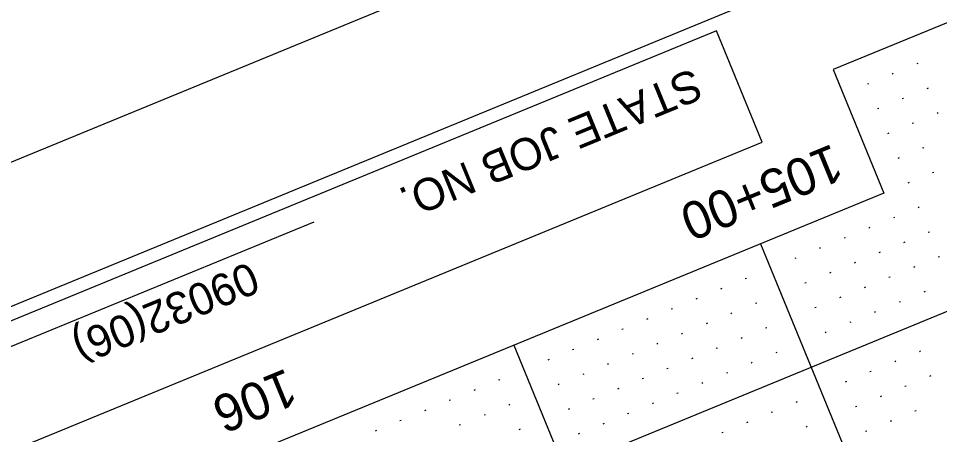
# Model space of a CAD drawing. Extents: x 2148770 to 2150891, y 142633 to 144465.
# Drawn here: x 2148940.4 to 2149113.1, y 143698.4 to 143776.3 of the extents above; entities that cross this region are included whole.
import ezdxf

# ---------------------------------------------------------------- set-up
doc = ezdxf.new("R2010")
doc.units = 0
for name, color, linetype in [('SHT_Plan_Profile_Sheet_Sta_Txt', 7, 'Continuous'), ('SHT_Plan_Profile_Sheet_Txt', 7, 'Continuous'), ('SHT_Plot_Shape_Half', 7, 'Continuous'), ('SHT_Profile_Grid_Major', 7, 'Continuous'), ('SHT_Profile_Grid_Minor', 7, 'Continuous'), ('SHT_Sheet_Border', 7, 'Continuous'), ('SHT_Standard_Sheet_Lines', 7, 'Continuous')]:
    doc.layers.add(name, color=color, linetype=linetype)

msp = doc.modelspace()

# ---------------------------------------------------------------- linework, layer by layer
at = {"layer": 'SHT_Plot_Shape_Half'}
msp.add_lwpolyline([(2150799.14, 143324.02), (2149226.52, 142678.36), (2148808.74, 143695.93), (2150381.36, 144341.59)], close=True, dxfattribs=at)
at = {"layer": 'SHT_Profile_Grid_Major'}
for p, q in [((2150326.3, 144218.99), (2148869.31, 143620.81)), ((2149079.52, 143734.14), (2149259.93, 143294.73)), ((2149033.27, 143715.15), (2149213.67, 143275.74))]:
    msp.add_line(p, q, dxfattribs=at)
at = {"layer": 'SHT_Profile_Grid_Minor'}
for p, q in [((2149109.04, 143767.88), (2149108.81, 143767.78)), ((2149104.42, 143765.98), (2149104.19, 143765.88)), ((2149099.79, 143764.08), (2149099.56, 143763.98)), ((2149110.94, 143763.25), (2149110.71, 143763.16)), ((2149106.32, 143761.35), (2149106.09, 143761.26)), ((2149101.69, 143759.45), (2149101.46, 143759.36)), ((2149112.84, 143758.63), (2149112.61, 143758.53)), ((2149108.22, 143756.73), (2149107.98, 143756.63)), ((2149103.59, 143754.83), (2149103.36, 143754.73)), ((2149110.12, 143752.1), (2149109.88, 143752.01)), ((2149105.49, 143750.2), (2149105.26, 143750.11)), ((2149112.01, 143747.48), (2149111.78, 143747.38)), ((2149107.39, 143745.58), (2149107.16, 143745.48)), ((2149109.29, 143740.95), (2149109.06, 143740.86)), ((2149104.66, 143739.05), (2149104.43, 143738.96)), ((2149100.04, 143737.15), (2149099.81, 143737.06)), ((2149111.19, 143736.33), (2149110.96, 143736.23)), ((2149095.41, 143735.25), (2149095.18, 143735.16)), ((2149106.56, 143734.43), (2149106.33, 143734.33)), ((2149090.79, 143733.36), (2149090.56, 143733.26)), ((2149101.94, 143732.53), (2149101.7, 143732.43)), ((2149086.16, 143731.46), (2149085.93, 143731.36)), ((2149097.31, 143730.63), (2149097.08, 143730.53)), ((2149113.09, 143731.7), (2149112.85, 143731.61)), ((2149092.69, 143728.73), (2149092.45, 143728.64)), ((2149108.46, 143729.8), (2149108.23, 143729.71)), ((2149076.91, 143727.66), (2149076.68, 143727.56)), ((2149103.84, 143727.9), (2149103.6, 143727.81)), ((2149072.29, 143725.76), (2149072.05, 143725.66)), ((2149088.06, 143726.83), (2149087.83, 143726.74)), ((2149099.21, 143726), (2149098.98, 143725.91)), ((2149067.66, 143723.86), (2149067.43, 143723.77)), ((2149094.58, 143724.11), (2149094.35, 143724.01)), ((2149110.36, 143725.18), (2149110.13, 143725.08)), ((2149063.03, 143721.96), (2149062.8, 143721.87)), ((2149078.81, 143723.03), (2149078.58, 143722.94)), ((2149089.96, 143722.21), (2149089.73, 143722.11)), ((2149105.73, 143723.28), (2149105.5, 143723.18)), ((2149058.41, 143720.06), (2149058.18, 143719.97)), ((2149074.18, 143721.13), (2149073.95, 143721.04)), ((2149101.11, 143721.38), (2149100.88, 143721.28)), ((2149069.56, 143719.24), (2149069.33, 143719.14)), ((2149080.71, 143718.41), (2149080.48, 143718.31)), ((2149096.48, 143719.48), (2149096.25, 143719.38)), ((2149053.78, 143718.16), (2149053.55, 143718.07)), ((2149064.93, 143717.34), (2149064.7, 143717.24)), ((2149091.86, 143717.58), (2149091.63, 143717.49)), ((2149049.16, 143716.26), (2149048.93, 143716.17)), ((2149060.31, 143715.44), (2149060.08, 143715.34)), ((2149076.08, 143716.51), (2149075.85, 143716.41)), ((2149044.53, 143714.37), (2149044.3, 143714.27)), ((2149055.68, 143713.54), (2149055.45, 143713.44)), ((2149071.46, 143714.61), (2149071.23, 143714.52)), ((2149082.61, 143713.78), (2149082.38, 143713.69)), ((2149109.53, 143714.03), (2149109.3, 143713.93)), ((2149039.91, 143712.47), (2149039.68, 143712.37)), ((2149051.06, 143711.64), (2149050.83, 143711.54)), ((2149066.83, 143712.71), (2149066.6, 143712.62)), ((2149077.98, 143711.88), (2149077.75, 143711.79)), ((2149104.91, 143712.13), (2149104.68, 143712.03)), ((2149046.43, 143709.74), (2149046.2, 143709.65)), ((2149062.21, 143710.81), (2149061.98, 143710.72)), ((2149073.36, 143709.98), (2149073.13, 143709.89)), ((2149100.28, 143710.23), (2149100.05, 143710.13)), ((2149030.66, 143708.67), (2149030.43, 143708.57)), ((2149057.58, 143708.91), (2149057.35, 143708.82)), ((2149068.73, 143708.09), (2149068.5, 143707.99)), ((2149095.66, 143708.33), (2149095.42, 143708.23)), ((2149111.43, 143709.4), (2149111.2, 143709.31)), ((2149026.03, 143706.77), (2149025.8, 143706.67)), ((2149041.81, 143707.84), (2149041.58, 143707.75)), ((2149052.96, 143707.01), (2149052.73, 143706.92)), ((2149106.81, 143707.5), (2149106.57, 143707.41)), ((2149021.41, 143704.87), (2149021.18, 143704.78)), ((2149048.33, 143705.11), (2149048.1, 143705.02)), ((2149064.11, 143706.19), (2149063.87, 143706.09)), ((2149086.41, 143704.53), (2149086.17, 143704.44)), ((2149102.18, 143705.6), (2149101.95, 143705.51)), ((2149016.78, 143702.97), (2149016.55, 143702.88)), ((2149032.56, 143704.04), (2149032.32, 143703.95)), ((2149043.71, 143703.22), (2149043.47, 143703.12)), ((2149059.48, 143704.29), (2149059.25, 143704.19)), ((2149097.56, 143703.7), (2149097.32, 143703.61)), ((2149108.7, 143702.88), (2149108.47, 143702.78)), ((2149012.16, 143701.07), (2149011.92, 143700.98)), ((2149027.93, 143702.14), (2149027.7, 143702.05)), ((2149054.86, 143702.39), (2149054.62, 143702.29)), ((2149081.78, 143702.63), (2149081.55, 143702.54)), ((2149023.31, 143700.25), (2149023.07, 143700.15)), ((2149034.46, 143699.42), (2149034.22, 143699.32)), ((2149050.23, 143700.49), (2149050, 143700.39)), ((2149077.15, 143700.73), (2149076.92, 143700.64)), ((2149088.3, 143699.91), (2149088.07, 143699.81)), ((2149104.08, 143700.98), (2149103.85, 143700.88)), ((2149007.53, 143699.17), (2149007.3, 143699.08)), ((2149045.6, 143698.59), (2149045.37, 143698.5)), ((2149072.53, 143698.83), (2149072.3, 143698.74)), ((2149099.45, 143699.08), (2149099.22, 143698.98))]:
    msp.add_line(p, q, dxfattribs=at)
at = {"layer": 'SHT_Sheet_Border'}
msp.add_line((2150307.31, 144265.25), (2149093.15, 143766.76), dxfattribs=at)
for points in [[(2150699.45, 143310.11), (2149242.47, 142711.93), (2148843.68, 143683.25), (2150300.66, 144281.43)], [(2149079.81, 143753.17), (2149071.27, 143773.99), (2148846.94, 143681.89), (2148855.48, 143661.07)]]:
    msp.add_lwpolyline(points, close=True, dxfattribs=at)
msp.add_lwpolyline([(2149093.15, 143766.76), (2149102.65, 143743.63), (2148894.51, 143658.18)], dxfattribs=at)
at = {"layer": 'SHT_Standard_Sheet_Lines'}
msp.add_line((2148995.78, 143738.2), (2148928.52, 143710.58), dxfattribs=at)

# ---------------------------------------------------------------- texts
at = {"layer": 'SHT_Plan_Profile_Sheet_Sta_Txt'}
for s, p in [('105+00', (2149093.03, 143752.92)), ('106', (2148990.68, 143710.9))]:
    msp.add_text(s, height=7, rotation=202.3213, dxfattribs=at).set_placement(p)
at = {"layer": 'SHT_Plan_Profile_Sheet_Txt'}
for s, p in [('STATE JOB NO.', (2149066.96, 143767.09)), ('09032(06)', (2148983.86, 143730.87))]:
    msp.add_text(s, height=6, rotation=202.3213, dxfattribs=at).set_placement(p)

doc.saveas('drawing.dxf')
